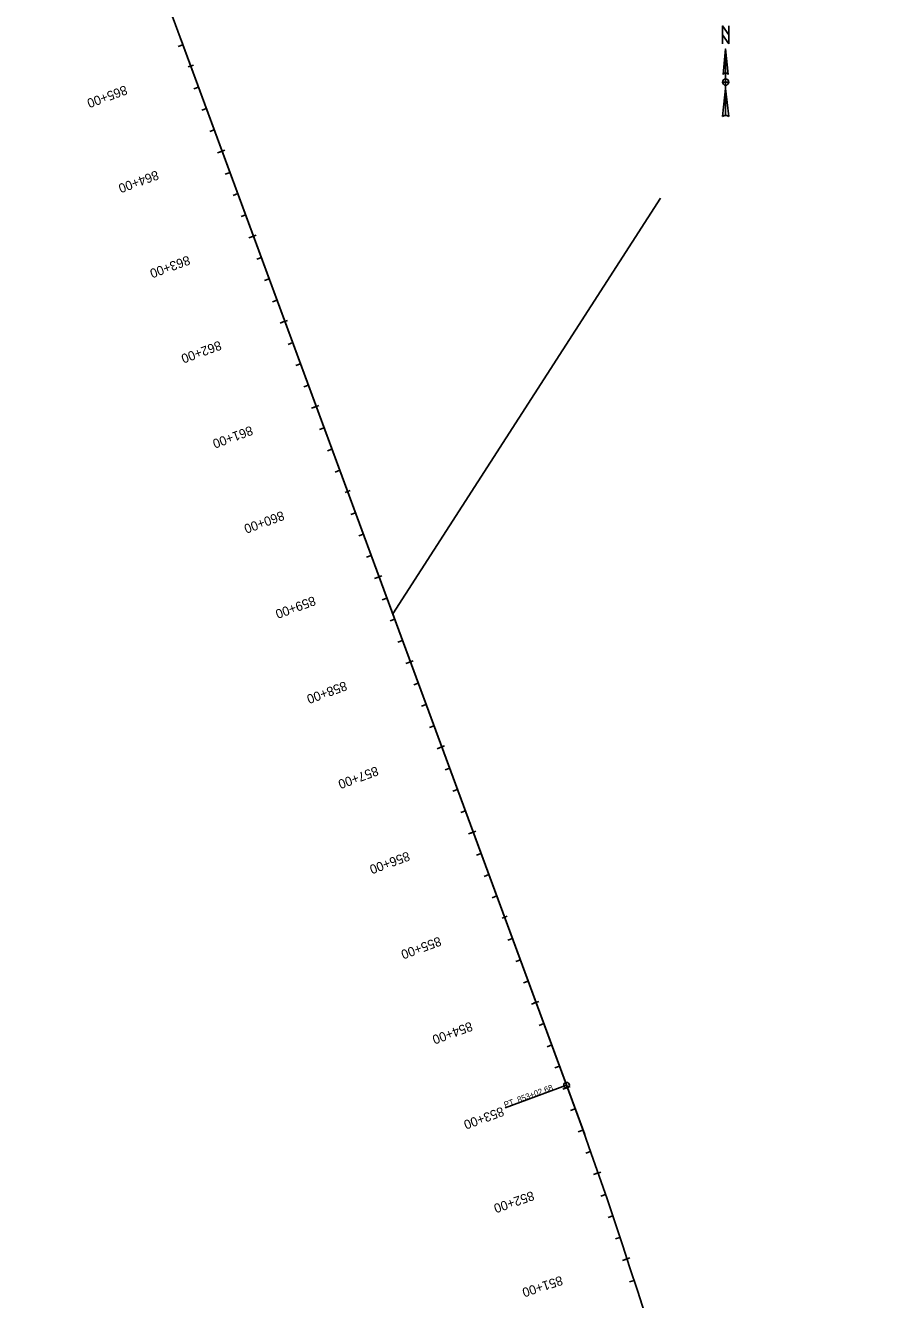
# Model space of a CAD drawing. Extents: x 2280195 to 2281869, y 391521 to 396826.
# Drawn here: x 2280864 to 2281801, y 394179 to 395583 of the extents above; entities that cross this region are included whole.
import ezdxf

# ---------------------------------------------------------------- set-up
doc = ezdxf.new("R2010")
doc.units = 0
for name, color, linetype in [('DisPropLines', 7, 'Continuous'), ('DisSecLines', 7, 'Continuous'), ('oleExistingMitigation', 7, 'Continuous'), ('oleFarmland', 7, 'Continuous'), ('olePrairies', 7, 'Continuous'), ('oleWildlife', 7, 'Continuous')]:
    doc.layers.add(name, color=color, linetype=linetype)

msp = doc.modelspace()

# ---------------------------------------------------------------- linework, layer by layer
at = {"layer": 'DisPropLines'}
msp.add_line((2281268.6, 394934.7), (2281563.7, 395392.9), dxfattribs=at)
at = {"layer": 'DisSecLines'}
for p, q in [((2281635.3, 395557.3), (2281638.1, 395529.1)), ((2281635.3, 395557.3), (2281635.3, 395484)), ((2281632.5, 395529.1), (2281632.5, 395529.1)), ((2281632.6, 395529.4), (2281633.1, 395530)), ((2281631.8, 395482.6), (2281635.3, 395513.6)), ((2281635.3, 395517.1), (2281635.3, 395517.1))]:
    msp.add_line(p, q, dxfattribs=at)
msp.add_lwpolyline([(2281638.8, 395562.9), (2281631.8, 395572.8), (2281631.8, 395582.6), (2281638.8, 395572.8)], close=True, dxfattribs=at)
for points in [[(2281631.8, 395562.9), (2281631.8, 395582.6), (2281638.8, 395572.8), (2281638.8, 395582.6)], [(2281632.5, 395529.1), (2281635.3, 395557.3), (2281635.3, 395530.5)], [(2281635.3, 395517.1), (2281635.3, 395520.7), (2281631.8, 395520.7)], [(2281638.8, 395520.7), (2281635.3, 395520.7), (2281635.3, 395524.2)], [(2281635.3, 395484), (2281635.3, 395513.6), (2281638.8, 395482.6)]]:
    msp.add_lwpolyline(points, dxfattribs=at)
for centre, radius, start, end in [((2281635.3, 395527), 3.52, 90.0204, 143.1257), ((2281635.3, 395527), 3.52, 36.8481, 90.0218), ((2281635.3, 395520.7), 3.52, 90, 180), ((2281635.3, 395520.7), 3.52, 180, 270), ((2281635.3, 395520.7), 3.52, 0, 90), ((2281635.3, 395520.7), 3.52, 270, 360), ((2281635.3, 395478.9), 5.1, 89.9894, 133.619), ((2281635.3, 395478.9), 5.11, 46.4021, 90.0006)]:
    msp.add_arc(centre, radius, start, end, dxfattribs=at)
at = {"layer": 'oleExistingMitigation'}
msp.add_line((2281460.1, 394415), (2281392.6, 394390.1), dxfattribs=at)
msp.add_circle((2281460.1, 394415), 3.12, dxfattribs=at)
at = {"layer": 'oleFarmland'}
for p, q in [((2281043.3, 395537.4), (2281049, 395539.5)), ((2281080.7, 395444.6), (2281075.6, 395442.8)), ((2281115.3, 395350.8), (2281110.2, 395348.9)), ((2281149.9, 395257), (2281144.7, 395255.1)), ((2281184.4, 395163.1), (2281179.3, 395161.3)), ((2281216.2, 395068.3), (2281221.9, 395070.4)), ((2281253.6, 394975.5), (2281248.5, 394973.6)), ((2281288.2, 394881.7), (2281283.1, 394879.8)), ((2281322.8, 394787.8), (2281317.6, 394785.9)), ((2281357.3, 394694), (2281352.2, 394692.1)), ((2281389, 394599.1), (2281394.8, 394601.2)), ((2281426.5, 394506.3), (2281421.4, 394504.4)), ((2281461.1, 394412.5), (2281455.9, 394410.6)), ((2281494.8, 394318.3), (2281489.6, 394316.5)), ((2281526.8, 394223.6), (2281521.6, 394221.9))]:
    msp.add_line(p, q, dxfattribs=at)
at = {"layer": 'olePrairies'}
for p, q in [((2281037.5, 395561.9), (2281032.4, 395560)), ((2281043.3, 395537.4), (2281049, 395539.5)), ((2281054.8, 395515), (2281049.7, 395513.1)), ((2281063.4, 395491.6), (2281058.3, 395489.7)), ((2281072.1, 395468.1), (2281067, 395466.2)), ((2281077.8, 395443.6), (2281083.6, 395445.7)), ((2281089.4, 395421.2), (2281084.2, 395419.3)), ((2281098, 395397.7), (2281092.9, 395395.8)), ((2281106.7, 395374.3), (2281101.5, 395372.4)), ((2281112.4, 395349.8), (2281118.2, 395351.9)), ((2281123.9, 395327.4), (2281118.8, 395325.5)), ((2281132.6, 395303.9), (2281127.5, 395302)), ((2281141.2, 395280.4), (2281136.1, 395278.5)), ((2281147, 395255.9), (2281152.7, 395258)), ((2281158.5, 395233.5), (2281153.4, 395231.6)), ((2281167.2, 395210.1), (2281162, 395208.2)), ((2281175.8, 395186.6), (2281170.7, 395184.7)), ((2281181.6, 395162.1), (2281187.3, 395164.2)), ((2281193.1, 395139.7), (2281188, 395137.8)), ((2281201.7, 395116.2), (2281196.6, 395114.3)), ((2281210.4, 395092.8), (2281205.3, 395090.9)), ((2281216.2, 395068.3), (2281221.9, 395070.4)), ((2281227.7, 395045.9), (2281222.5, 395044)), ((2281236.3, 395022.4), (2281231.2, 395020.5)), ((2281245, 394998.9), (2281239.8, 394997.1)), ((2281250.7, 394974.4), (2281256.5, 394976.5)), ((2281262.2, 394952), (2281257.1, 394950.1)), ((2281270.9, 394928.6), (2281265.8, 394926.7)), ((2281279.5, 394905.1), (2281274.4, 394903.2)), ((2281285.3, 394880.6), (2281291, 394882.7)), ((2281296.8, 394858.2), (2281291.7, 394856.3)), ((2281305.5, 394834.7), (2281300.3, 394832.8)), ((2281314.1, 394811.3), (2281309, 394809.4)), ((2281319.9, 394786.8), (2281325.6, 394788.9)), ((2281331.4, 394764.4), (2281326.3, 394762.5)), ((2281340, 394740.9), (2281334.9, 394739)), ((2281348.7, 394717.4), (2281343.6, 394715.6)), ((2281354.5, 394692.9), (2281360.2, 394695)), ((2281366, 394670.5), (2281360.9, 394668.6)), ((2281374.6, 394647.1), (2281369.5, 394645.2)), ((2281383.3, 394623.6), (2281378.1, 394621.7)), ((2281389, 394599.1), (2281394.8, 394601.2)), ((2281400.6, 394576.7), (2281395.4, 394574.8)), ((2281409.2, 394553.2), (2281404.1, 394551.3)), ((2281417.8, 394529.8), (2281412.7, 394527.9)), ((2281423.6, 394505.3), (2281429.4, 394507.4)), ((2281435.1, 394482.9), (2281430, 394481)), ((2281443.8, 394459.4), (2281438.6, 394457.5)), ((2281452.4, 394435.9), (2281447.3, 394434.1)), ((2281458.2, 394411.4), (2281463.9, 394413.5)), ((2281469.6, 394389), (2281464.5, 394387.1)), ((2281478.1, 394365.5), (2281473, 394363.6)), ((2281486.5, 394341.9), (2281481.3, 394340.1)), ((2281491.9, 394317.3), (2281497.7, 394319.3)), ((2281502.9, 394294.7), (2281497.8, 394292.9)), ((2281511, 394271), (2281505.8, 394269.3)), ((2281518.9, 394247.3), (2281513.8, 394245.6)), ((2281523.9, 394222.7), (2281529.7, 394224.6)), ((2281534.5, 394199.8), (2281529.3, 394198.2))]:
    msp.add_line(p, q, dxfattribs=at)
at = {"layer": 'oleWildlife'}
for p, q in [((2281460.1, 394415), (2280864.1, 396032.4)), ((2281034.8, 395569.2), (2281480.1, 394360.8))]:
    msp.add_line(p, q, dxfattribs=at)
msp.add_arc((2276149.2, 392458), 5660, 3.0064, 20.2285, dxfattribs=at)
msp.add_arc((2276149.2, 392458), 5660, 3.0064, 20.2285, dxfattribs=at)

# ---------------------------------------------------------------- texts
at = {"layer": 'oleExistingMitigation'}
for s, p in [('853+02.68', (2281407.1, 394395.6)), ('PT', (2281392.5, 394390.2))]:
    msp.add_text(s, height=6.48, rotation=20.2285, dxfattribs=at).set_placement(p)
at = {"layer": 'oleFarmland'}
for s, p in [('865+00', (2280974, 395517.3)), ('860+00', (2281146.9, 395048.2)), ('855+00', (2281319.8, 394579))]:
    msp.add_text(s, height=10.2, rotation=200.2285, dxfattribs=at).set_placement(p)
at = {"layer": 'olePrairies'}
for s, rotation, p in [('865+00', 200.2285, (2280974, 395517.3)), ('864+00', 200.2285, (2281008.6, 395423.5)), ('863+00', 200.2285, (2281043.2, 395329.7)), ('862+00', 200.2285, (2281077.7, 395235.8)), ('861+00', 200.2285, (2281112.3, 395142)), ('860+00', 200.2285, (2281146.9, 395048.2)), ('859+00', 200.2285, (2281181.5, 394954.3)), ('858+00', 200.2285, (2281216, 394860.5)), ('857+00', 200.2285, (2281250.6, 394766.7)), ('856+00', 200.2285, (2281285.2, 394672.8)), ('855+00', 200.2285, (2281319.8, 394579)), ('854+00', 200.2285, (2281354.3, 394485.2)), ('853+00', 200.2014, (2281388.9, 394391.4)), ('852+00', 199.1891, (2281422.3, 394298.5)), ('851+00', 198.1768, (2281453.9, 394205.1))]:
    msp.add_text(s, height=10.2, rotation=rotation, dxfattribs=at).set_placement(p)

doc.saveas('drawing.dxf')
